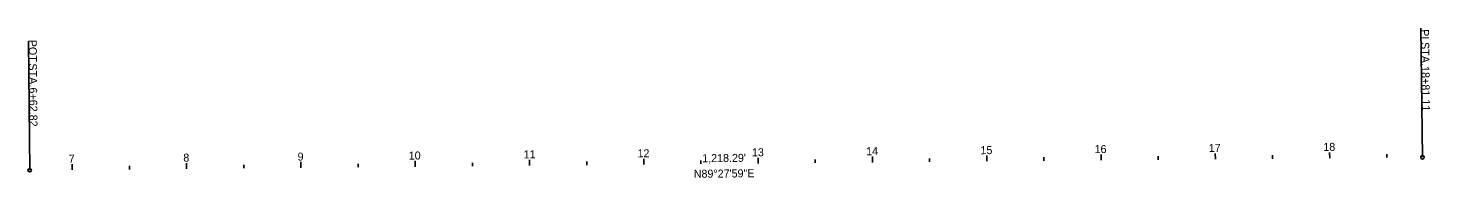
# Model space of a CAD drawing. Extents: x 1805326 to 1810276, y 297762 to 303660.
# Drawn here: x 1805326 to 1806552, y 298327 to 298458 of the extents above; entities that cross this region are included whole.
import ezdxf

# ---------------------------------------------------------------- set-up
doc = ezdxf.new("R2010")
doc.units = 0
for name, color, linetype in [('GE_P_Alignment_100_Bearings', 7, 'Continuous'), ('GE_P_Alignment_100_Cardinal_Points', 7, 'Continuous'), ('GE_P_Alignment_100_Distances', 7, 'Continuous'), ('GE_P_Alignment_100_Stations', 7, 'Continuous')]:
    doc.layers.add(name, color=color, linetype=linetype)

msp = doc.modelspace()

# ---------------------------------------------------------------- linework, layer by layer
at = {"layer": 'GE_P_Alignment_100_Cardinal_Points'}
for p, q in [((1806545.4, 298345.4), (1806543.9, 298457.9)), ((1805327.1, 298334.1), (1805326.1, 298446.6))]:
    msp.add_line(p, q, dxfattribs=at)
for centre in [(1806545.4, 298345.4), (1805327.1, 298334.1)]:
    msp.add_circle(centre, 1.5, dxfattribs=at)
at = {"layer": 'GE_P_Alignment_100_Stations'}
for p, q in [((1806264.3, 298342.8), (1806264.2, 298347.8)), ((1806364.3, 298343.8), (1806364.2, 298348.8)), ((1806414.3, 298344.2), (1806414.2, 298347.2)), ((1806464.3, 298344.7), (1806464.2, 298349.7)), ((1806514.3, 298345.2), (1806514.2, 298348.2)), ((1805364.3, 298334.4), (1805364.3, 298339.4)), ((1805414.3, 298334.9), (1805414.3, 298337.9)), ((1805464.3, 298335.4), (1805464.3, 298340.4)), ((1805514.3, 298335.8), (1805514.3, 298338.8)), ((1805564.3, 298336.3), (1805564.3, 298341.3)), ((1805614.3, 298336.8), (1805614.3, 298339.8)), ((1805664.3, 298337.2), (1805664.3, 298342.2)), ((1805714.3, 298337.7), (1805714.3, 298340.7)), ((1805764.3, 298338.2), (1805764.3, 298343.2)), ((1805814.3, 298338.6), (1805814.3, 298341.6)), ((1805864.3, 298339.1), (1805864.3, 298344.1)), ((1805914.3, 298339.6), (1805914.3, 298342.6)), ((1805964.3, 298340), (1805964.2, 298345)), ((1806014.3, 298340.5), (1806014.3, 298343.5)), ((1806064.3, 298341), (1806064.2, 298346)), ((1806114.3, 298341.4), (1806114.3, 298344.4)), ((1806164.3, 298341.9), (1806164.2, 298346.9)), ((1806214.3, 298342.4), (1806214.3, 298345.4)), ((1806314.3, 298343.3), (1806314.3, 298346.3))]:
    msp.add_line(p, q, dxfattribs=at)

# ---------------------------------------------------------------- texts
at = {"layer": 'GE_P_Alignment_100_Bearings'}
msp.add_text('N89°27\'59"E', height=7, rotation=0.5335, dxfattribs=at).set_placement((1805908, 298327.5))
at = {"layer": 'GE_P_Alignment_100_Cardinal_Points'}
for s, rotation, p in [('POT', 270.5335, (1805326.2, 298447.8)), ('PI', 270.7316, (1806544.1, 298456.9)), (' STA. ', 270.7316, (1806544.2, 298448.4)), (' STA. ', 270.5335, (1805326.4, 298429.8)), ('18+81.11', 270.7316, (1806544.5, 298424.8)), ('6+62.82', 270.5335, (1805326.6, 298406.2))]:
    msp.add_text(s, height=7, rotation=rotation, dxfattribs=at).set_placement(p)
at = {"layer": 'GE_P_Alignment_100_Distances'}
msp.add_text("1,218.29'", height=7, rotation=0.5335, dxfattribs=at).set_placement((1805915.4, 298341.1))
at = {"layer": 'GE_P_Alignment_100_Stations'}
for s, p in [('7', (1805361.3, 298340.7)), ('8', (1805461.5, 298341.6)), ('9', (1805561.5, 298342.5)), ('10', (1805658.7, 298343.4)), ('11', (1805759.2, 298344.4)), ('12', (1805858.8, 298345.3)), ('13', (1805958.9, 298346.2)), ('14', (1806058.8, 298347.2)), ('15', (1806158.8, 298348.1)), ('16', (1806258.6, 298349)), ('17', (1806358.5, 298350)), ('18', (1806458.7, 298350.9))]:
    msp.add_text(s, height=7, rotation=0.5335, dxfattribs=at).set_placement(p)

doc.saveas('drawing.dxf')
